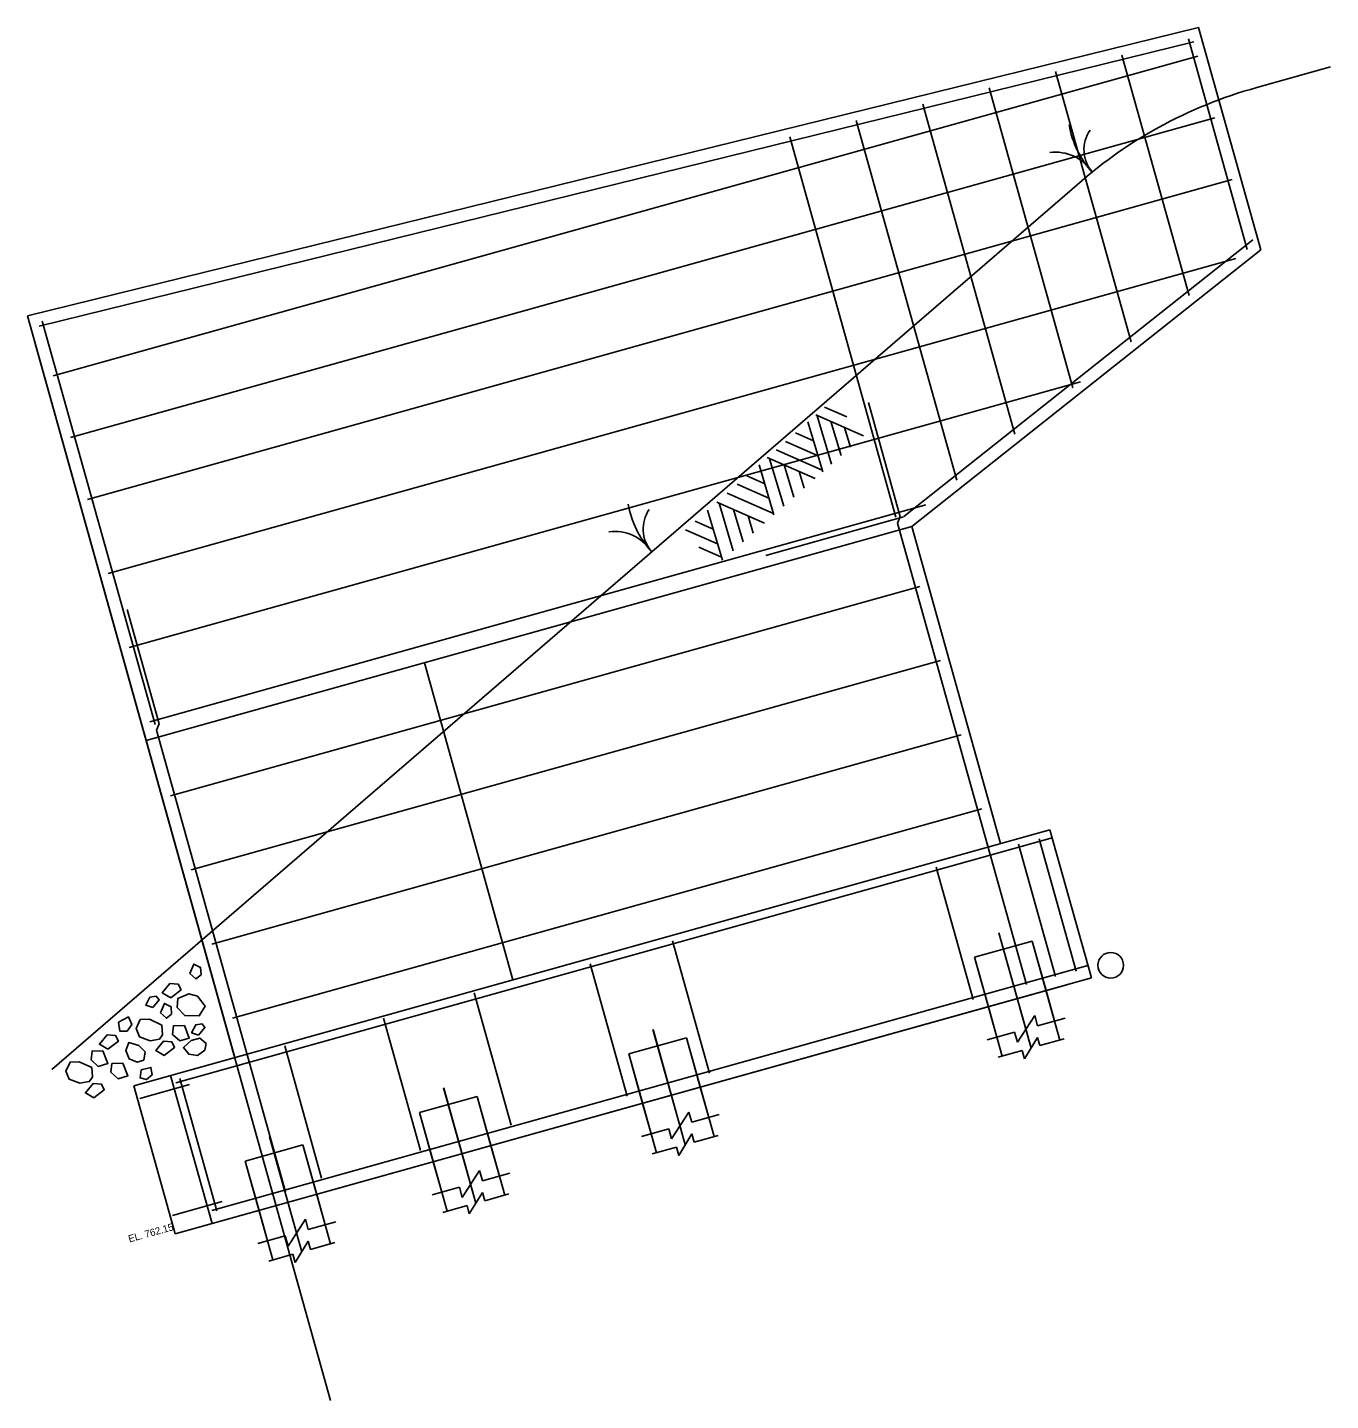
# Model space of a CAD drawing. Extents: x 1539537 to 1543620, y 586918 to 587494.
# Drawn here: x 1543163.62 to 1543189.02, y 587241.69 to 587268.46 of the extents above; entities that cross this region are included whole.
import ezdxf

# ---------------------------------------------------------------- set-up
doc = ezdxf.new("R2010")
doc.units = 0
for name, color, linetype in [('BR_P_Gen_Ground_Slope', 7, 'Continuous'), ('BR_P_Gen_Text', 7, 'Continuous'), ('BR_P_Sub_Const_Joint', 7, 'Continuous'), ('BR_P_Sub_Deep_Centerline', 7, 'Continuous'), ('BR_P_Sub_Deep_Hidden', 7, 'Continuous'), ('BR_P_Sub_Deep_Object', 7, 'Continuous'), ('BR_P_Sub_Foot_Object', 7, 'Continuous'), ('BR_P_Sub_Hidden', 7, 'Continuous'), ('BR_P_Sub_Object', 7, 'Continuous'), ('BR_P_Sub_Reinforcing', 7, 'Continuous'), ('RD_P_Text', 7, 'Continuous'), ('SC_Scratch14', 7, 'Continuous'), ('SC_Shading1', 7, 'Continuous')]:
    doc.layers.add(name, color=color, linetype=linetype)

msp = doc.modelspace()

# ---------------------------------------------------------------- linework, layer by layer
at = {"layer": 'BR_P_Gen_Ground_Slope'}
for p, q in [((1543187.585, 587267.286), (1543189.023, 587267.688)), ((1543164.095, 587248.145), (1543183.986, 587265.304))]:
    msp.add_line(p, q, dxfattribs=at)
for centre, radius, start, end in [((1543189.926, 587258.775), 8.827, 105.3764, 132.2936), ((1543185.72, 587266.862), 1.818, 189.5596, 222.441), ((1543184.894, 587266.074), 0.677, 145.6033, 220.3926), ((1543183.661, 587265.175), 0.852, 32.7203, 97.5152), ((1543177.127, 587259.469), 1.818, 189.5596, 222.441), ((1543176.301, 587258.681), 0.677, 145.6033, 220.3926), ((1543175.068, 587257.782), 0.852, 32.7203, 97.5152)]:
    msp.add_arc(centre, radius, start, end, dxfattribs=at)
at = {"layer": 'BR_P_Gen_Text'}
for p, q in [((1543182.921, 587248.673), (1543183.258, 587249.197)), ((1543183.258, 587249.197), (1543183.314, 587248.997)), ((1543183.314, 587248.997), (1543183.848, 587249.147)), ((1543182.331, 587248.723), (1543182.865, 587248.872)), ((1543182.865, 587248.872), (1543182.921, 587248.673)), ((1543183.059, 587248.352), (1543183.312, 587248.77)), ((1543183.312, 587248.77), (1543183.357, 587248.609)), ((1543183.828, 587248.74), (1543183.357, 587248.609)), ((1543183.014, 587248.513), (1543182.543, 587248.382)), ((1543183.014, 587248.513), (1543183.059, 587248.352)), ((1543176.179, 587246.789), (1543176.516, 587247.313)), ((1543176.516, 587247.313), (1543176.572, 587247.114)), ((1543176.572, 587247.114), (1543177.106, 587247.263)), ((1543175.589, 587246.839), (1543176.123, 587246.988)), ((1543176.123, 587246.988), (1543176.179, 587246.789)), ((1543176.317, 587246.468), (1543176.571, 587246.886)), ((1543176.571, 587246.886), (1543176.616, 587246.725)), ((1543177.086, 587246.857), (1543176.616, 587246.725)), ((1543176.272, 587246.629), (1543175.802, 587246.498)), ((1543176.272, 587246.629), (1543176.317, 587246.468)), ((1543172.098, 587245.649), (1543172.436, 587246.173)), ((1543172.436, 587246.173), (1543172.491, 587245.974)), ((1543172.491, 587245.974), (1543173.026, 587246.123)), ((1543171.509, 587245.699), (1543172.043, 587245.848)), ((1543172.043, 587245.848), (1543172.098, 587245.649)), ((1543172.236, 587245.328), (1543172.49, 587245.746)), ((1543172.49, 587245.746), (1543172.535, 587245.585)), ((1543172.191, 587245.489), (1543171.721, 587245.358)), ((1543172.191, 587245.489), (1543172.236, 587245.328)), ((1543173.005, 587245.717), (1543172.535, 587245.585)), ((1543168.705, 587244.701), (1543169.042, 587245.224)), ((1543169.042, 587245.224), (1543169.097, 587245.025)), ((1543169.097, 587245.025), (1543169.632, 587245.174)), ((1543168.115, 587244.751), (1543168.649, 587244.9)), ((1543168.649, 587244.9), (1543168.705, 587244.701)), ((1543168.843, 587244.38), (1543169.096, 587244.798)), ((1543169.096, 587244.798), (1543169.141, 587244.637)), ((1543169.611, 587244.768), (1543169.141, 587244.637)), ((1543168.798, 587244.541), (1543168.327, 587244.409)), ((1543168.798, 587244.541), (1543168.843, 587244.38))]:
    msp.add_line(p, q, dxfattribs=at)
at = {"layer": 'BR_P_Sub_Const_Joint'}
msp.add_line((1543180.864, 587258.728), (1543165.936, 587254.557), dxfattribs=at)
at = {"layer": 'BR_P_Sub_Deep_Centerline'}
for p, q in [((1543182.557, 587250.81), (1543183.127, 587248.771)), ((1543182.558, 587250.805), (1543183.186, 587248.561)), ((1543175.815, 587248.926), (1543176.385, 587246.887)), ((1543175.817, 587248.922), (1543176.444, 587246.677)), ((1543171.735, 587247.786), (1543172.305, 587245.747)), ((1543171.736, 587247.782), (1543172.363, 587245.537)), ((1543168.341, 587246.837), (1543168.911, 587244.799)), ((1543168.342, 587246.833), (1543168.969, 587244.589))]:
    msp.add_line(p, q, dxfattribs=at)
at = {"layer": 'BR_P_Sub_Deep_Hidden'}
for p, q in [((1543183.209, 587250.644), (1543182.085, 587250.33)), ((1543183.209, 587250.644), (1543182.085, 587250.33)), ((1543183.209, 587250.644), (1543183.747, 587248.718)), ((1543183.478, 587249.681), (1543183.209, 587250.644)), ((1543182.085, 587250.33), (1543182.624, 587248.404)), ((1543182.355, 587249.367), (1543182.085, 587250.33)), ((1543176.467, 587248.76), (1543175.344, 587248.446)), ((1543176.467, 587248.76), (1543175.344, 587248.446)), ((1543176.467, 587248.76), (1543177.006, 587246.834)), ((1543176.736, 587247.797), (1543176.467, 587248.76)), ((1543175.344, 587248.446), (1543175.882, 587246.52)), ((1543175.613, 587247.483), (1543175.344, 587248.446)), ((1543172.387, 587247.62), (1543171.263, 587247.306)), ((1543172.387, 587247.62), (1543171.263, 587247.306)), ((1543172.387, 587247.62), (1543172.925, 587245.694)), ((1543172.656, 587246.657), (1543172.387, 587247.62)), ((1543171.263, 587247.306), (1543171.801, 587245.38)), ((1543171.532, 587246.343), (1543171.263, 587247.306)), ((1543168.993, 587246.672), (1543167.869, 587246.358)), ((1543168.993, 587246.672), (1543167.869, 587246.358)), ((1543168.993, 587246.672), (1543169.531, 587244.746)), ((1543169.262, 587245.709), (1543168.993, 587246.672)), ((1543167.869, 587246.358), (1543168.408, 587244.432)), ((1543168.138, 587245.395), (1543167.869, 587246.358))]:
    msp.add_line(p, q, dxfattribs=at)
at = {"layer": 'BR_P_Sub_Deep_Object'}
for p, q in [((1543183.478, 587249.681), (1543183.643, 587249.09)), ((1543182.355, 587249.367), (1543182.52, 587248.776)), ((1543176.736, 587247.797), (1543176.902, 587247.206)), ((1543175.613, 587247.483), (1543175.778, 587246.892)), ((1543172.656, 587246.657), (1543172.821, 587246.066)), ((1543171.532, 587246.343), (1543171.698, 587245.752)), ((1543169.262, 587245.709), (1543169.427, 587245.117)), ((1543168.138, 587245.395), (1543168.304, 587244.803))]:
    msp.add_line(p, q, dxfattribs=at)
msp.add_circle((1543184.739, 587250.175), 0.25, dxfattribs=at)
at = {"layer": 'BR_P_Sub_Foot_Object'}
for p, q in [((1543183.554, 587252.817), (1543165.696, 587247.827)), ((1543183.554, 587252.817), (1543184.361, 587249.928)), ((1543166.503, 587244.938), (1543184.361, 587249.928)), ((1543166.503, 587244.938), (1543184.361, 587249.928)), ((1543183.88, 587249.793), (1543166.503, 587244.938)), ((1543167.221, 587245.139), (1543166.413, 587248.028)), ((1543166.503, 587244.938), (1543165.696, 587247.827))]:
    msp.add_line(p, q, dxfattribs=at)
at = {"layer": 'BR_P_Sub_Hidden'}
msp.add_line((1543173.086, 587249.892), (1543171.359, 587256.072), dxfattribs=at)
at = {"layer": 'BR_P_Sub_Object'}
for p, q in [((1543163.623, 587262.835), (1543186.452, 587268.458)), ((1543186.452, 587268.458), (1543187.663, 587264.124)), ((1543187.663, 587264.124), (1543180.864, 587258.728)), ((1543167.662, 587248.377), (1543163.623, 587262.835)), ((1543182.591, 587252.548), (1543180.864, 587258.728))]:
    msp.add_line(p, q, dxfattribs=at)
at = {"layer": 'BR_P_Sub_Reinforcing'}
for p, q in [((1543186.254, 587268.238), (1543187.401, 587264.13)), ((1543163.852, 587262.634), (1543186.357, 587268.177)), ((1543164.123, 587261.664), (1543186.435, 587267.899)), ((1543184.958, 587267.919), (1543186.268, 587263.23)), ((1543183.663, 587267.6), (1543185.135, 587262.331)), ((1543182.368, 587267.28), (1543184.002, 587261.432)), ((1543181.073, 587266.961), (1543182.869, 587260.532)), ((1543164.459, 587260.461), (1543186.771, 587266.695)), ((1543179.777, 587266.642), (1543181.736, 587259.633)), ((1543178.482, 587266.323), (1543180.552, 587258.914)), ((1543164.795, 587259.257), (1543187.108, 587265.491)), ((1543187.507, 587264.32), (1543180.708, 587258.924)), ((1543165.199, 587257.812), (1543187.18, 587263.954)), ((1543163.91, 587262.734), (1543166.109, 587254.867)), ((1543165.603, 587256.367), (1543184.151, 587261.55)), ((1543180.637, 587258.919), (1543180.015, 587261.147)), ((1543166.006, 587254.923), (1543181.136, 587259.15)), ((1543180.698, 587258.915), (1543178.015, 587258.166)), ((1543180.585, 587258.797), (1543180.637, 587258.919)), ((1543183.1, 587249.797), (1543180.585, 587258.797)), ((1543166.41, 587253.478), (1543181.017, 587257.559)), ((1543166.191, 587254.882), (1543165.568, 587257.11)), ((1543166.814, 587252.033), (1543181.421, 587256.115)), ((1543166.138, 587254.76), (1543166.191, 587254.882)), ((1543168.653, 587245.76), (1543166.138, 587254.76)), ((1543168.653, 587245.76), (1543166.138, 587254.76)), ((1543167.217, 587250.589), (1543181.825, 587254.67)), ((1543167.621, 587249.144), (1543182.228, 587253.225)), ((1543183.599, 587252.657), (1543166.513, 587247.883)), ((1543182.94, 587252.534), (1543183.661, 587249.957)), ((1543183.344, 587252.637), (1543184.065, 587250.06)), ((1543181.335, 587252.086), (1543182.056, 587249.508)), ((1543176.199, 587250.651), (1543176.919, 587248.073)), ((1543167.217, 587245.397), (1543184.294, 587250.169)), ((1543174.594, 587250.202), (1543175.314, 587247.624)), ((1543174.594, 587250.202), (1543175.314, 587247.624)), ((1543172.329, 587249.636), (1543173.049, 587247.058)), ((1543170.563, 587249.143), (1543171.284, 587246.565)), ((1543168.637, 587248.604), (1543169.357, 587246.027)), ((1543166.592, 587247.966), (1543167.312, 587245.389)), ((1543165.813, 587247.581), (1543166.781, 587247.851)), ((1543166.452, 587245.297), (1543167.419, 587245.567))]:
    msp.add_line(p, q, dxfattribs=at)
at = {"layer": 'SC_Scratch14'}
msp.add_line((1543169.531, 587241.689), (1543163.76, 587262.342), dxfattribs=at)
at = {"layer": 'SC_Shading1'}
for p, q in [((1543179.594, 587260.865), (1543179.161, 587261.057)), ((1543179.125, 587259.795), (1543178.833, 587260.771)), ((1543179.92, 587260.496), (1543178.989, 587260.905)), ((1543179.296, 587259.946), (1543179.015, 587260.889)), ((1543179.486, 587260.113), (1543179.285, 587260.773)), ((1543178.945, 587260.401), (1543178.594, 587260.557)), ((1543179.668, 587260.274), (1543179.552, 587260.657)), ((1543179.116, 587259.825), (1543178.214, 587260.221)), ((1543179.033, 587260.107), (1543178.401, 587260.386)), ((1543178.978, 587259.666), (1543178.044, 587260.072)), ((1543178.364, 587259.124), (1543178.089, 587260.05)), ((1543177.986, 587259.566), (1543177.644, 587259.719)), ((1543178.173, 587258.955), (1543177.883, 587259.929)), ((1543178.562, 587259.298), (1543178.372, 587259.929)), ((1543178.764, 587259.476), (1543178.664, 587259.801)), ((1543178.073, 587259.284), (1543177.459, 587259.556)), ((1543177.992, 587258.796), (1543177.06, 587259.204)), ((1543177.377, 587258.254), (1543177.103, 587259.185)), ((1543178.164, 587258.982), (1543177.259, 587259.38)), ((1543177.171, 587258.072), (1543176.881, 587259.046)), ((1543177.575, 587258.428), (1543177.388, 587259.061)), ((1543177.771, 587258.601), (1543177.67, 587258.936)), ((1543177.076, 587258.393), (1543176.449, 587258.666)), ((1543176.992, 587258.674), (1543176.638, 587258.832)), ((1543177.153, 587258.132), (1543176.712, 587258.324))]:
    msp.add_line(p, q, dxfattribs=at)
for points in [[(1543166.787, 587250.017), (1543166.865, 587250.199), (1543166.996, 587250.133), (1543167.006, 587249.99), (1543166.905, 587249.908), (1543166.787, 587250.017)], [(1543166.415, 587249.54), (1543166.249, 587249.639), (1543166.398, 587249.818), (1543166.563, 587249.806), (1543166.617, 587249.698), (1543166.415, 587249.54)], [(1543166.066, 587249.351), (1543165.928, 587249.397), (1543166.01, 587249.553), (1543166.132, 587249.57), (1543166.189, 587249.5), (1543166.066, 587249.351)], [(1543166.938, 587249.576), (1543167.087, 587249.381), (1543166.97, 587249.191), (1543166.689, 587249.193), (1543166.538, 587249.355), (1543166.556, 587249.529), (1543166.768, 587249.618), (1543166.938, 587249.576)], [(1543166.214, 587249.25), (1543166.291, 587249.432), (1543166.422, 587249.365), (1543166.432, 587249.223), (1543166.331, 587249.141), (1543166.214, 587249.25)], [(1543165.395, 587249.067), (1543165.59, 587249.169), (1543165.656, 587249.02), (1543165.564, 587248.891), (1543165.42, 587248.891), (1543165.395, 587249.067)], [(1543165.999, 587249.122), (1543166.244, 587249.006), (1543166.258, 587248.821), (1543166.195, 587248.733), (1543166.013, 587248.704), (1543165.806, 587248.779), (1543165.741, 587248.94), (1543165.821, 587249.117), (1543165.999, 587249.122)], [(1543166.681, 587249.003), (1543166.777, 587248.757), (1543166.59, 587248.699), (1543166.448, 587248.825), (1543166.468, 587248.997), (1543166.681, 587249.003)], [(1543166.959, 587248.814), (1543166.821, 587248.86), (1543166.902, 587249.016), (1543167.025, 587249.033), (1543167.081, 587248.963), (1543166.959, 587248.814)], [(1543165.192, 587248.538), (1543165.026, 587248.637), (1543165.176, 587248.816), (1543165.341, 587248.804), (1543165.395, 587248.696), (1543165.192, 587248.538)], [(1543166.288, 587248.416), (1543166.122, 587248.515), (1543166.272, 587248.694), (1543166.437, 587248.682), (1543166.49, 587248.574), (1543166.288, 587248.416)], [(1543166.814, 587248.71), (1543166.98, 587248.754), (1543167.104, 587248.648), (1543167.078, 587248.518), (1543166.94, 587248.415), (1543166.768, 587248.44), (1543166.662, 587248.571), (1543166.814, 587248.71)], [(1543165.095, 587248.508), (1543165.19, 587248.262), (1543165.003, 587248.204), (1543164.862, 587248.33), (1543164.881, 587248.502), (1543165.095, 587248.508)], [(1543165.796, 587248.609), (1543165.917, 587248.488), (1543165.888, 587248.327), (1543165.763, 587248.284), (1543165.604, 587248.352), (1543165.539, 587248.513), (1543165.599, 587248.67), (1543165.796, 587248.609)], [(1543164.63, 587248.295), (1543164.875, 587248.179), (1543164.889, 587247.994), (1543164.826, 587247.906), (1543164.644, 587247.876), (1543164.437, 587247.952), (1543164.372, 587248.113), (1543164.452, 587248.289), (1543164.63, 587248.295)], [(1543165.484, 587248.266), (1543165.58, 587248.02), (1543165.393, 587247.962), (1543165.251, 587248.088), (1543165.27, 587248.26), (1543165.484, 587248.266)], [(1543165.836, 587248.139), (1543166.028, 587248.185), (1543166.053, 587248.041), (1543165.945, 587247.948), (1543165.819, 587247.979), (1543165.836, 587248.139)], [(1543164.919, 587247.588), (1543164.753, 587247.688), (1543164.903, 587247.867), (1543165.068, 587247.855), (1543165.121, 587247.747), (1543164.919, 587247.588)]]:
    msp.add_lwpolyline(points, dxfattribs=at)

# ---------------------------------------------------------------- texts
at = {"layer": 'RD_P_Text'}
msp.add_text('EL. 762.15', height=0.14, rotation=15.6111, dxfattribs=at).set_placement((1543165.61, 587244.77))

doc.saveas('drawing.dxf')
